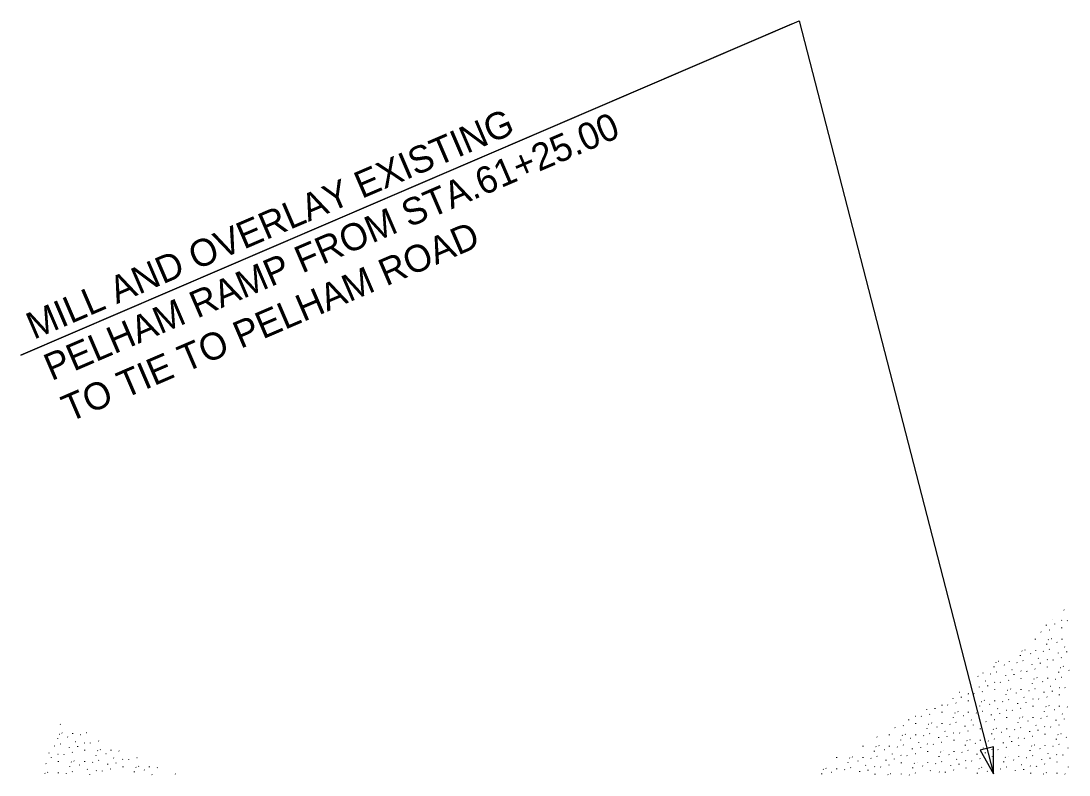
# Model space of a CAD drawing. Extents: x 1621035 to 1623496, y 1102384 to 1103996.
# Drawn here: x 1621952.8 to 1622185.9, y 1102744 to 1102911.6 of the extents above; entities that cross this region are included whole.
import ezdxf

# ---------------------------------------------------------------- set-up
doc = ezdxf.new("R2010")
doc.units = 0
doc.layers.add('RD_EX_RW', color=7, linetype='Continuous')

msp = doc.modelspace()

# ---------------------------------------------------------------- linework, layer by layer
at = {"layer": 'RD_EX_RW'}
for p, q in [((1622124.18, 1102910.93), (1621952.78, 1102837.37)), ((1622184.69, 1102780.73), (1622184.76, 1102780.68)), ((1622182.24, 1102778.71), (1622182.27, 1102778.69)), ((1622184.19, 1102778.43), (1622184.26, 1102778.38)), ((1622185.49, 1102778.4), (1622185.54, 1102778.31)), ((1622179.63, 1102775.89), (1622179.68, 1102775.79)), ((1622180.88, 1102777.29), (1622180.88, 1102777.41)), ((1622181.48, 1102776.34), (1622181.55, 1102776.29)), ((1622182.75, 1102777.56), (1622182.75, 1102777.68)), ((1622184.3, 1102776.71), (1622184.3, 1102776.83)), ((1622178.44, 1102774.19), (1622178.44, 1102774.31)), ((1622180.96, 1102773.06), (1622180.96, 1102773.18)), ((1622181.26, 1102774.16), (1622181.33, 1102774.11)), ((1622181.9, 1102774.4), (1622181.97, 1102774.36)), ((1622183.14, 1102773.55), (1622183.21, 1102773.5)), ((1622184.32, 1102774.2), (1622184.32, 1102774.32)), ((1622175.4, 1102771.64), (1622175.47, 1102771.6)), ((1622176.04, 1102771.89), (1622176.11, 1102771.84)), ((1622177.28, 1102771.03), (1622177.35, 1102770.98)), ((1622178.46, 1102771.69), (1622178.46, 1102771.81)), ((1622180.14, 1102771.57), (1622180.21, 1102771.53)), ((1622181.49, 1102772.01), (1622181.56, 1102771.97)), ((1622183.54, 1102771.09), (1622183.54, 1102771.21)), ((1622184.86, 1102772.53), (1622184.93, 1102772.49)), ((1622185.41, 1102771.36), (1622185.41, 1102771.48)), ((1622169.6, 1102769.09), (1622169.61, 1102769.08)), ((1622170.18, 1102769.37), (1622170.25, 1102769.32)), ((1622171.42, 1102768.52), (1622171.49, 1102768.47)), ((1622172.6, 1102769.17), (1622172.6, 1102769.29)), ((1622174.28, 1102769.06), (1622174.35, 1102769.01)), ((1622175.1, 1102770.55), (1622175.1, 1102770.67)), ((1622175.63, 1102769.5), (1622175.7, 1102769.45)), ((1622177.68, 1102768.58), (1622177.68, 1102768.69)), ((1622179, 1102770.02), (1622179.07, 1102769.97)), ((1622179.55, 1102768.84), (1622179.55, 1102768.96)), ((1622180.99, 1102769.71), (1622181.06, 1102769.67)), ((1622182.29, 1102769.69), (1622182.34, 1102769.6)), ((1622184.14, 1102770.14), (1622184.21, 1102770.09)), ((1622166.74, 1102766.66), (1622166.74, 1102766.78)), ((1622168.42, 1102766.54), (1622168.49, 1102766.5)), ((1622169.24, 1102768.03), (1622169.24, 1102768.15)), ((1622169.77, 1102766.98), (1622169.84, 1102766.94)), ((1622173.14, 1102767.5), (1622173.21, 1102767.46)), ((1622173.69, 1102766.33), (1622173.69, 1102766.45)), ((1622175.12, 1102767.2), (1622175.2, 1102767.15)), ((1622176.43, 1102767.18), (1622176.48, 1102767.08)), ((1622178.28, 1102767.62), (1622178.35, 1102767.58)), ((1622181.1, 1102768), (1622181.1, 1102768.11)), ((1622183.62, 1102766.86), (1622183.62, 1102766.98)), ((1622183.92, 1102767.96), (1622183.99, 1102767.91)), ((1622184.56, 1102768.2), (1622184.63, 1102768.16)), ((1622185.8, 1102767.35), (1622185.87, 1102767.3)), ((1622163.91, 1102764.47), (1622163.98, 1102764.42)), ((1622165.56, 1102766), (1622165.63, 1102765.95)), ((1622167.28, 1102764.99), (1622167.35, 1102764.94)), ((1622167.83, 1102763.81), (1622167.83, 1102763.93)), ((1622169.26, 1102764.68), (1622169.34, 1102764.64)), ((1622170.57, 1102764.66), (1622170.62, 1102764.57)), ((1622171.82, 1102766.06), (1622171.82, 1102766.18)), ((1622172.42, 1102765.11), (1622172.49, 1102765.06)), ((1622175.24, 1102765.48), (1622175.24, 1102765.6)), ((1622177.76, 1102764.35), (1622177.76, 1102764.47)), ((1622178.06, 1102765.44), (1622178.13, 1102765.4)), ((1622178.7, 1102765.69), (1622178.77, 1102765.64)), ((1622179.94, 1102764.83), (1622180.01, 1102764.79)), ((1622181.12, 1102765.49), (1622181.12, 1102765.61)), ((1622182.8, 1102765.38), (1622182.87, 1102765.33)), ((1622184.15, 1102765.82), (1622184.22, 1102765.77)), ((1622161.42, 1102762.47), (1622161.49, 1102762.43)), ((1622163.4, 1102762.17), (1622163.48, 1102762.12)), ((1622164.71, 1102762.15), (1622164.76, 1102762.05)), ((1622165.96, 1102763.55), (1622165.96, 1102763.66)), ((1622166.56, 1102762.59), (1622166.63, 1102762.55)), ((1622169.38, 1102762.97), (1622169.38, 1102763.08)), ((1622171.9, 1102761.83), (1622171.9, 1102761.95)), ((1622172.2, 1102762.93), (1622172.27, 1102762.88)), ((1622172.84, 1102763.17), (1622172.91, 1102763.13)), ((1622174.08, 1102762.32), (1622174.15, 1102762.27)), ((1622175.26, 1102762.98), (1622175.26, 1102763.09)), ((1622176.94, 1102762.86), (1622177.01, 1102762.81)), ((1622178.29, 1102763.3), (1622178.36, 1102763.25)), ((1622180.34, 1102762.38), (1622180.34, 1102762.5)), ((1622181.66, 1102763.82), (1622181.73, 1102763.77)), ((1622182.21, 1102762.64), (1622182.21, 1102762.76)), ((1622183.65, 1102763.51), (1622183.72, 1102763.47)), ((1622183.76, 1102761.8), (1622183.76, 1102761.92)), ((1622184.95, 1102763.49), (1622185, 1102763.4)), ((1622157.54, 1102759.65), (1622157.62, 1102759.6)), ((1622158.84, 1102759.63), (1622158.9, 1102759.54)), ((1622160.1, 1102761.03), (1622160.1, 1102761.15)), ((1622160.7, 1102760.08), (1622160.77, 1102760.03)), ((1622161.97, 1102761.3), (1622161.97, 1102761.42)), ((1622163.52, 1102760.45), (1622163.52, 1102760.57)), ((1622166.04, 1102759.32), (1622166.04, 1102759.44)), ((1622166.34, 1102760.41), (1622166.41, 1102760.37)), ((1622166.98, 1102760.66), (1622167.05, 1102760.61)), ((1622168.22, 1102759.8), (1622168.29, 1102759.75)), ((1622169.4, 1102760.46), (1622169.4, 1102760.58)), ((1622171.08, 1102760.35), (1622171.15, 1102760.3)), ((1622172.43, 1102760.79), (1622172.5, 1102760.74)), ((1622174.48, 1102759.86), (1622174.48, 1102759.98)), ((1622175.8, 1102761.31), (1622175.87, 1102761.26)), ((1622176.35, 1102760.13), (1622176.35, 1102760.25)), ((1622177.79, 1102761), (1622177.86, 1102760.95)), ((1622177.9, 1102759.28), (1622177.9, 1102759.4)), ((1622179.09, 1102760.98), (1622179.14, 1102760.88)), ((1622180.72, 1102759.25), (1622180.79, 1102759.2)), ((1622180.94, 1102761.43), (1622181.01, 1102761.38)), ((1622181.36, 1102759.49), (1622181.43, 1102759.44)), ((1622183.78, 1102759.29), (1622183.78, 1102759.41)), ((1622151.68, 1102757.14), (1622151.76, 1102757.09)), ((1622152.98, 1102757.11), (1622153.04, 1102757.02)), ((1622154.24, 1102758.52), (1622154.24, 1102758.57)), ((1622154.84, 1102757.56), (1622154.91, 1102757.52)), ((1622156.11, 1102758.78), (1622156.11, 1102758.9)), ((1622157.66, 1102757.93), (1622157.66, 1102758.05)), ((1622160.18, 1102756.8), (1622160.18, 1102756.92)), ((1622160.48, 1102757.9), (1622160.55, 1102757.85)), ((1622161.12, 1102758.14), (1622161.19, 1102758.1)), ((1622162.36, 1102757.29), (1622162.43, 1102757.24)), ((1622163.54, 1102757.94), (1622163.54, 1102758.06)), ((1622165.22, 1102757.83), (1622165.29, 1102757.78)), ((1622166.57, 1102758.27), (1622166.64, 1102758.22)), ((1622168.62, 1102757.35), (1622168.62, 1102757.47)), ((1622169.94, 1102758.79), (1622170.01, 1102758.74)), ((1622170.49, 1102757.61), (1622170.49, 1102757.73)), ((1622171.92, 1102758.48), (1622172, 1102758.44)), ((1622172.04, 1102756.77), (1622172.04, 1102756.88)), ((1622173.23, 1102758.46), (1622173.28, 1102758.37)), ((1622175.08, 1102758.91), (1622175.15, 1102758.86)), ((1622175.5, 1102756.98), (1622175.57, 1102756.93)), ((1622177.92, 1102756.78), (1622177.92, 1102756.89)), ((1622180.42, 1102758.15), (1622180.42, 1102758.27)), ((1622180.95, 1102757.1), (1622181.02, 1102757.06)), ((1622182.6, 1102758.63), (1622182.67, 1102758.59)), ((1622184.32, 1102757.62), (1622184.39, 1102757.58)), ((1622185.46, 1102759.18), (1622185.53, 1102759.13)), ((1621961.48, 1102755.32), (1621961.55, 1102755.27)), ((1622147.12, 1102754.6), (1622147.18, 1102754.51)), ((1622148.98, 1102755.05), (1622149.05, 1102755)), ((1622150.25, 1102756.27), (1622150.25, 1102756.39)), ((1622151.8, 1102755.42), (1622151.8, 1102755.54)), ((1622154.62, 1102755.38), (1622154.69, 1102755.34)), ((1622155.26, 1102755.63), (1622155.33, 1102755.58)), ((1622156.5, 1102754.77), (1622156.57, 1102754.72)), ((1622157.68, 1102755.43), (1622157.68, 1102755.55)), ((1622159.36, 1102755.32), (1622159.43, 1102755.27)), ((1622160.71, 1102755.76), (1622160.78, 1102755.71)), ((1622162.76, 1102754.83), (1622162.76, 1102754.95)), ((1622164.08, 1102756.28), (1622164.15, 1102756.23)), ((1622164.63, 1102755.1), (1622164.63, 1102755.22)), ((1622166.06, 1102755.97), (1622166.14, 1102755.92)), ((1622167.37, 1102755.95), (1622167.42, 1102755.85)), ((1622169.22, 1102756.4), (1622169.29, 1102756.35)), ((1622174.56, 1102755.64), (1622174.56, 1102755.75)), ((1622174.86, 1102756.73), (1622174.93, 1102756.68)), ((1622175.09, 1102754.59), (1622175.16, 1102754.54)), ((1622176.74, 1102756.12), (1622176.81, 1102756.07)), ((1622178.46, 1102755.11), (1622178.53, 1102755.06)), ((1622179.6, 1102756.66), (1622179.67, 1102756.62)), ((1622180.45, 1102754.8), (1622180.52, 1102754.75)), ((1622181.75, 1102754.78), (1622181.8, 1102754.68)), ((1622183, 1102756.18), (1622183, 1102756.3)), ((1622183.6, 1102755.23), (1622183.67, 1102755.18)), ((1622184.87, 1102756.45), (1622184.87, 1102756.56)), ((1621961.26, 1102753.14), (1621961.34, 1102753.09)), ((1621961.9, 1102753.39), (1621961.97, 1102753.34)), ((1621963.14, 1102752.53), (1621963.22, 1102752.48)), ((1621964.32, 1102753.19), (1621964.32, 1102753.31)), ((1621966, 1102753.07), (1621966.07, 1102753.03)), ((1621967.35, 1102753.51), (1621967.43, 1102753.47)), ((1622143.12, 1102752.53), (1622143.19, 1102752.49)), ((1622145.94, 1102752.9), (1622145.94, 1102753.02)), ((1622148.76, 1102752.87), (1622148.83, 1102752.82)), ((1622149.4, 1102753.11), (1622149.47, 1102753.07)), ((1622150.64, 1102752.26), (1622150.71, 1102752.21)), ((1622151.82, 1102752.91), (1622151.82, 1102753.03)), ((1622153.5, 1102752.8), (1622153.57, 1102752.75)), ((1622154.32, 1102754.29), (1622154.32, 1102754.41)), ((1622154.85, 1102753.24), (1622154.92, 1102753.19)), ((1622156.9, 1102752.32), (1622156.9, 1102752.44)), ((1622158.22, 1102753.76), (1622158.29, 1102753.71)), ((1622158.77, 1102752.58), (1622158.77, 1102752.7)), ((1622160.2, 1102753.45), (1622160.28, 1102753.41)), ((1622161.51, 1102753.43), (1622161.56, 1102753.34)), ((1622163.36, 1102753.88), (1622163.43, 1102753.83)), ((1622166.18, 1102754.25), (1622166.18, 1102754.37)), ((1622168.7, 1102753.12), (1622168.7, 1102753.24)), ((1622169, 1102754.22), (1622169.07, 1102754.17)), ((1622169.64, 1102754.46), (1622169.71, 1102754.41)), ((1622170.88, 1102753.6), (1622170.95, 1102753.56)), ((1622172.06, 1102754.26), (1622172.06, 1102754.38)), ((1622172.6, 1102752.59), (1622172.67, 1102752.54)), ((1622173.74, 1102754.15), (1622173.81, 1102754.1)), ((1622174.59, 1102752.29), (1622174.66, 1102752.24)), ((1622175.89, 1102752.26), (1622175.94, 1102752.17)), ((1622177.14, 1102753.66), (1622177.14, 1102753.78)), ((1622177.74, 1102752.71), (1622177.81, 1102752.67)), ((1622179.01, 1102753.93), (1622179.01, 1102754.05)), ((1622180.56, 1102753.08), (1622180.56, 1102753.2)), ((1622183.38, 1102753.05), (1622183.45, 1102753)), ((1622184.02, 1102753.29), (1622184.09, 1102753.24)), ((1622185.26, 1102752.44), (1622185.33, 1102752.39)), ((1621960.14, 1102750.56), (1621960.21, 1102750.51)), ((1621960.96, 1102752.05), (1621960.97, 1102752.16)), ((1621961.49, 1102751), (1621961.57, 1102750.95)), ((1621963.54, 1102750.07), (1621963.55, 1102750.19)), ((1621964.87, 1102751.52), (1621964.94, 1102751.47)), ((1621965.41, 1102750.34), (1621965.41, 1102750.46)), ((1621966.85, 1102751.21), (1621966.92, 1102751.16)), ((1621968.15, 1102751.19), (1621968.2, 1102751.09)), ((1621970, 1102751.64), (1621970.08, 1102751.59)), ((1622140.08, 1102750.39), (1622140.08, 1102750.51)), ((1622142.9, 1102750.35), (1622142.97, 1102750.31)), ((1622143.54, 1102750.6), (1622143.61, 1102750.55)), ((1622145.96, 1102750.4), (1622145.96, 1102750.52)), ((1622147.64, 1102750.29), (1622147.71, 1102750.24)), ((1622148.46, 1102751.77), (1622148.46, 1102751.89)), ((1622148.99, 1102750.72), (1622149.06, 1102750.68)), ((1622151.04, 1102749.8), (1622151.04, 1102749.92)), ((1622152.36, 1102751.24), (1622152.43, 1102751.2)), ((1622152.91, 1102750.07), (1622152.91, 1102750.19)), ((1622154.34, 1102750.94), (1622154.42, 1102750.89)), ((1622155.64, 1102750.92), (1622155.7, 1102750.82)), ((1622157.5, 1102751.37), (1622157.57, 1102751.32)), ((1622160.32, 1102751.74), (1622160.32, 1102751.85)), ((1622162.84, 1102750.6), (1622162.84, 1102750.72)), ((1622163.14, 1102751.7), (1622163.21, 1102751.65)), ((1622163.78, 1102751.94), (1622163.85, 1102751.9)), ((1622165.02, 1102751.09), (1622165.09, 1102751.04)), ((1622166.2, 1102751.75), (1622166.2, 1102751.86)), ((1622166.74, 1102750.08), (1622166.81, 1102750.03)), ((1622167.88, 1102751.63), (1622167.95, 1102751.59)), ((1622169.23, 1102752.07), (1622169.3, 1102752.02)), ((1622171.28, 1102751.15), (1622171.28, 1102751.27)), ((1622171.88, 1102750.2), (1622171.95, 1102750.15)), ((1622173.15, 1102751.42), (1622173.15, 1102751.53)), ((1622174.7, 1102750.57), (1622174.7, 1102750.69)), ((1622177.52, 1102750.53), (1622177.59, 1102750.49)), ((1622178.16, 1102750.78), (1622178.23, 1102750.73)), ((1622179.4, 1102749.92), (1622179.47, 1102749.87)), ((1622180.58, 1102750.58), (1622180.58, 1102750.7)), ((1622182.26, 1102750.46), (1622182.33, 1102750.42)), ((1622183.08, 1102751.95), (1622183.08, 1102752.07)), ((1622183.61, 1102750.9), (1622183.68, 1102750.86)), ((1622185.66, 1102749.98), (1622185.66, 1102750.1)), ((1621959, 1102749), (1621959.08, 1102748.96)), ((1621959.55, 1102747.83), (1621959.55, 1102747.94)), ((1621960.99, 1102748.7), (1621961.06, 1102748.65)), ((1621962.29, 1102748.67), (1621962.34, 1102748.58)), ((1621964.14, 1102749.12), (1621964.22, 1102749.08)), ((1621966.96, 1102749.49), (1621966.97, 1102749.61)), ((1621969.48, 1102748.36), (1621969.49, 1102748.48)), ((1621969.78, 1102749.46), (1621969.86, 1102749.41)), ((1621970.42, 1102749.7), (1621970.49, 1102749.66)), ((1621971.66, 1102748.85), (1621971.74, 1102748.8)), ((1621972.84, 1102749.5), (1621972.84, 1102749.62)), ((1621973.39, 1102747.83), (1621973.46, 1102747.79)), ((1621974.52, 1102749.39), (1621974.59, 1102749.34)), ((1621978.52, 1102747.96), (1621978.6, 1102747.91)), ((1622134.22, 1102747.87), (1622134.22, 1102747.99)), ((1622137.04, 1102747.84), (1622137.11, 1102747.79)), ((1622137.67, 1102748.08), (1622137.75, 1102748.04)), ((1622140.1, 1102747.88), (1622140.1, 1102748)), ((1622141.77, 1102747.77), (1622141.85, 1102747.72)), ((1622142.6, 1102749.26), (1622142.6, 1102749.38)), ((1622143.13, 1102748.21), (1622143.2, 1102748.16)), ((1622144.78, 1102749.74), (1622144.85, 1102749.69)), ((1622146.5, 1102748.73), (1622146.57, 1102748.68)), ((1622147.05, 1102747.55), (1622147.05, 1102747.67)), ((1622148.48, 1102748.42), (1622148.56, 1102748.38)), ((1622149.78, 1102748.4), (1622149.84, 1102748.31)), ((1622151.64, 1102748.85), (1622151.71, 1102748.8)), ((1622154.46, 1102749.22), (1622154.46, 1102749.34)), ((1622156.98, 1102748.09), (1622156.98, 1102748.21)), ((1622157.28, 1102749.19), (1622157.35, 1102749.14)), ((1622157.92, 1102749.43), (1622157.99, 1102749.38)), ((1622159.16, 1102748.57), (1622159.23, 1102748.53)), ((1622160.34, 1102749.23), (1622160.34, 1102749.35)), ((1622160.88, 1102747.56), (1622160.95, 1102747.51)), ((1622162.02, 1102749.12), (1622162.09, 1102749.07)), ((1622163.37, 1102749.56), (1622163.44, 1102749.51)), ((1622165.42, 1102748.63), (1622165.42, 1102748.75)), ((1622166.02, 1102747.68), (1622166.09, 1102747.63)), ((1622167.29, 1102748.9), (1622167.29, 1102749.02)), ((1622168.72, 1102749.77), (1622168.8, 1102749.72)), ((1622168.84, 1102748.05), (1622168.84, 1102748.17)), ((1622170.03, 1102749.75), (1622170.08, 1102749.65)), ((1622171.66, 1102748.02), (1622171.73, 1102747.97)), ((1622172.3, 1102748.26), (1622172.37, 1102748.21)), ((1622174.72, 1102748.06), (1622174.72, 1102748.18)), ((1622176.4, 1102747.95), (1622176.47, 1102747.9)), ((1622177.22, 1102749.44), (1622177.22, 1102749.56)), ((1622177.75, 1102748.39), (1622177.82, 1102748.34)), ((1622179.8, 1102747.47), (1622179.8, 1102747.58)), ((1622181.12, 1102748.91), (1622181.19, 1102748.86)), ((1622181.67, 1102747.73), (1622181.67, 1102747.85)), ((1622183.11, 1102748.6), (1622183.18, 1102748.56)), ((1622184.41, 1102748.58), (1622184.46, 1102748.49)), ((1621958.28, 1102746.61), (1621958.35, 1102746.56)), ((1621961.1, 1102746.98), (1621961.11, 1102747.1)), ((1621963.62, 1102745.85), (1621963.63, 1102745.97)), ((1621963.92, 1102746.94), (1621964, 1102746.9)), ((1621964.56, 1102747.19), (1621964.63, 1102747.14)), ((1621965.8, 1102746.33), (1621965.88, 1102746.28)), ((1621966.98, 1102746.99), (1621966.98, 1102747.11)), ((1621967.53, 1102745.32), (1621967.6, 1102745.27)), ((1621968.66, 1102746.87), (1621968.73, 1102746.83)), ((1621970.02, 1102747.31), (1621970.09, 1102747.27)), ((1621972.07, 1102746.39), (1621972.07, 1102746.51)), ((1621972.66, 1102745.44), (1621972.74, 1102745.39)), ((1621973.93, 1102746.66), (1621973.94, 1102746.78)), ((1621975.37, 1102747.53), (1621975.44, 1102747.48)), ((1621975.48, 1102745.81), (1621975.49, 1102745.93)), ((1621976.67, 1102747.51), (1621976.73, 1102747.41)), ((1621978.3, 1102745.78), (1621978.38, 1102745.73)), ((1621978.94, 1102746.02), (1621979.02, 1102745.97)), ((1621981.36, 1102745.82), (1621981.36, 1102745.94)), ((1621983.04, 1102745.71), (1621983.12, 1102745.66)), ((1622131.18, 1102745.32), (1622131.25, 1102745.28)), ((1622131.81, 1102745.57), (1622131.89, 1102745.52)), ((1622134.23, 1102745.37), (1622134.24, 1102745.49)), ((1622135.91, 1102745.25), (1622135.99, 1102745.21)), ((1622136.74, 1102746.74), (1622136.74, 1102746.86)), ((1622137.27, 1102745.69), (1622137.34, 1102745.65)), ((1622138.92, 1102747.23), (1622138.99, 1102747.18)), ((1622140.64, 1102746.21), (1622140.71, 1102746.17)), ((1622142.62, 1102745.91), (1622142.7, 1102745.86)), ((1622143.92, 1102745.89), (1622143.98, 1102745.79)), ((1622145.18, 1102747.29), (1622145.18, 1102747.4)), ((1622145.78, 1102746.33), (1622145.85, 1102746.29)), ((1622148.6, 1102746.71), (1622148.6, 1102746.82)), ((1622151.12, 1102745.57), (1622151.12, 1102745.69)), ((1622151.42, 1102746.67), (1622151.49, 1102746.62)), ((1622152.06, 1102746.91), (1622152.13, 1102746.87)), ((1622153.3, 1102746.06), (1622153.37, 1102746.01)), ((1622154.48, 1102746.72), (1622154.48, 1102746.83)), ((1622156.16, 1102746.6), (1622156.23, 1102746.55)), ((1622157.51, 1102747.04), (1622157.58, 1102746.99)), ((1622159.56, 1102746.12), (1622159.56, 1102746.24)), ((1622161.43, 1102746.39), (1622161.43, 1102746.5)), ((1622162.86, 1102747.26), (1622162.94, 1102747.21)), ((1622162.98, 1102745.54), (1622162.98, 1102745.66)), ((1622164.17, 1102747.23), (1622164.22, 1102747.14)), ((1622165.8, 1102745.5), (1622165.87, 1102745.45)), ((1622166.44, 1102745.75), (1622166.51, 1102745.7)), ((1622168.86, 1102745.55), (1622168.86, 1102745.67)), ((1622170.54, 1102745.43), (1622170.61, 1102745.39)), ((1622171.36, 1102746.92), (1622171.36, 1102747.04)), ((1622171.89, 1102745.87), (1622171.96, 1102745.83)), ((1622173.54, 1102747.41), (1622173.61, 1102747.36)), ((1622175.26, 1102746.39), (1622175.33, 1102746.35)), ((1622175.81, 1102745.22), (1622175.81, 1102745.34)), ((1622177.25, 1102746.09), (1622177.32, 1102746.04)), ((1622178.55, 1102746.07), (1622178.6, 1102745.97)), ((1622180.4, 1102746.51), (1622180.47, 1102746.47)), ((1622183.22, 1102746.89), (1622183.22, 1102747)), ((1622185.74, 1102745.75), (1622185.74, 1102745.87)), ((1621958.06, 1102744.43), (1621958.14, 1102744.38)), ((1621958.7, 1102744.67), (1621958.77, 1102744.62)), ((1621961.12, 1102744.47), (1621961.12, 1102744.59)), ((1621962.8, 1102744.36), (1621962.87, 1102744.31)), ((1621964.15, 1102744.8), (1621964.23, 1102744.75)), ((1621968.07, 1102744.14), (1621968.07, 1102744.26)), ((1621969.51, 1102745.01), (1621969.58, 1102744.97)), ((1621970.81, 1102744.99), (1621970.86, 1102744.9)), ((1621978.01, 1102744.68), (1621978.01, 1102744.8)), ((1621980.19, 1102745.16), (1621980.26, 1102745.12)), ((1621981.91, 1102744.15), (1621981.98, 1102744.1)), ((1621987.04, 1102744.27), (1621987.12, 1102744.22)), ((1622130.88, 1102744.23), (1622130.88, 1102744.35)), ((1622133.06, 1102744.71), (1622133.13, 1102744.66)), ((1622139.32, 1102744.77), (1622139.32, 1102744.89)), ((1622141.19, 1102745.04), (1622141.19, 1102745.16)), ((1622142.74, 1102744.19), (1622142.74, 1102744.31)), ((1622145.56, 1102744.16), (1622145.63, 1102744.11)), ((1622146.2, 1102744.4), (1622146.27, 1102744.35)), ((1622148.62, 1102744.2), (1622148.62, 1102744.32)), ((1622150.3, 1102744.09), (1622150.37, 1102744.04)), ((1622151.65, 1102744.53), (1622151.72, 1102744.48)), ((1622155.02, 1102745.05), (1622155.09, 1102745)), ((1622157, 1102744.74), (1622157.08, 1102744.69)), ((1622158.3, 1102744.72), (1622158.36, 1102744.62)), ((1622160.16, 1102745.17), (1622160.23, 1102745.12)), ((1622165.5, 1102744.41), (1622165.5, 1102744.52)), ((1622167.68, 1102744.89), (1622167.75, 1102744.84)), ((1622173.94, 1102744.95), (1622173.94, 1102745.07)), ((1622177.36, 1102744.37), (1622177.36, 1102744.49)), ((1622180.18, 1102744.33), (1622180.25, 1102744.29)), ((1622180.82, 1102744.58), (1622180.89, 1102744.53)), ((1622183.24, 1102744.38), (1622183.24, 1102744.5)), ((1622184.92, 1102744.27), (1622184.99, 1102744.22))]:
    msp.add_line(p, q, dxfattribs=at)
msp.add_lwpolyline([(1621952.78, 1102837.37), (1622125.84, 1102911.65), (1622169.06, 1102744.33)], dxfattribs=at)
msp.add_lwpolyline([(1622166.11, 1102749.56), (1622169.06, 1102744.33), (1622169.11, 1102750.33)], close=True, dxfattribs=at)

# ---------------------------------------------------------------- texts
for s, p in [('MILL AND OVERLAY EXISTING', (1621955.64, 1102840.77)), ('PELHAM RAMP FROM STA.61+25.00 ', (1621959.58, 1102831.58)), ('TO TIE TO PELHAM ROAD', (1621963.53, 1102822.39))]:
    msp.add_text(s, height=6, rotation=23.2284, dxfattribs=at).set_placement(p)

doc.saveas('drawing.dxf')
